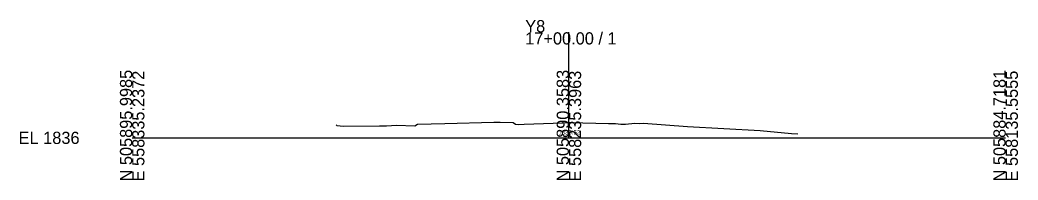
# Model space of a CAD drawing. Extents: x -26 to 203, y -10 to 8070.
# Drawn here: x -25.7 to 202.8, y 6990.3 to 7027.1 of the extents above; entities that cross this region are included whole.
import ezdxf

# ---------------------------------------------------------------- set-up
doc = ezdxf.new("R2010")
doc.units = 0
for name, color, linetype in [('Default', 7, 'Continuous'), ('Exist Cross Section Cell', 7, 'Continuous'), ('Exist XS Center Line Elevation Label', 7, 'Continuous'), ('Exist XS Ground Line', 7, 'Continuous')]:
    doc.layers.add(name, color=color, linetype=linetype)

msp = doc.modelspace()

# ---------------------------------------------------------------- linework, layer by layer
at = {"layer": 'Exist Cross Section Cell'}
for p, q in [((100, 7000), (100, 7024.22)), ((0, 7000), (100, 7000)), ((100, 7000), (200, 7000))]:
    msp.add_line(p, q, dxfattribs=at)
at = {"layer": 'Exist XS Ground Line'}
for p, q in [((46.71, 7002.96), (46.85, 7002.81)), ((46.85, 7002.81), (48.41, 7002.68)), ((48.41, 7002.68), (56.65, 7002.79)), ((56.65, 7002.79), (58.21, 7002.77)), ((58.21, 7002.77), (60.49, 7002.88)), ((60.49, 7002.88), (64.75, 7002.76)), ((64.75, 7002.76), (65.37, 7003.1)), ((65.37, 7003.1), (71.6, 7003.3)), ((71.6, 7003.3), (82.78, 7003.6)), ((82.78, 7003.6), (83.64, 7003.59)), ((83.64, 7003.59), (84.28, 7003.59)), ((84.28, 7003.59), (87.22, 7003.55)), ((87.22, 7003.55), (87.81, 7003.14)), ((87.81, 7003.14), (88.51, 7003.07)), ((88.51, 7003.07), (89.73, 7003.14)), ((89.73, 7003.14), (98.63, 7003.47)), ((98.63, 7003.47), (100, 7003.52)), ((100, 7003.52), (100.32, 7003.53)), ((100.32, 7003.53), (109.07, 7003.31)), ((109.07, 7003.31), (110.66, 7003.26)), ((110.66, 7003.26), (111.86, 7003.17)), ((111.86, 7003.17), (112.98, 7003.16)), ((112.98, 7003.16), (115.08, 7003.34)), ((115.08, 7003.34), (116.07, 7003.28)), ((116.07, 7003.28), (117.09, 7003.39)), ((117.09, 7003.39), (127.14, 7002.63)), ((127.14, 7002.63), (143.79, 7001.68)), ((143.79, 7001.68), (150.94, 7001)), ((150.94, 7001), (152.43, 7000.9))]:
    msp.add_line(p, q, dxfattribs=at)

# ---------------------------------------------------------------- texts
at = {"layer": 'Default'}
msp.add_text('-', height=0.0001, dxfattribs=at).set_placement((0, 7000))
at = {"layer": 'Exist Cross Section Cell'}
for s, p in [('Y8', (90, 7024.22)), ('17+00.00 / 1', (90, 7021.42)), ('EL 1836', (-26, 6998.6))]:
    msp.add_text(s, height=2.8, dxfattribs=at).set_placement(p)
for s, p in [('N 505895.9985', (0, 6990)), ('E 558335.2372', (2.8, 6990)), ('N 505890.3583', (100, 6990)), ('E 558235.3963', (102.8, 6990)), ('N 505884.7181', (200, 6990)), ('E 558135.5555', (202.8, 6990))]:
    msp.add_text(s, height=2.8, rotation=90, dxfattribs=at).set_placement(p)
at = {"layer": 'Exist XS Center Line Elevation Label'}
msp.add_text('1839.52', height=1, dxfattribs=at).set_placement((97.6, 7000.77))

doc.saveas('drawing.dxf')
